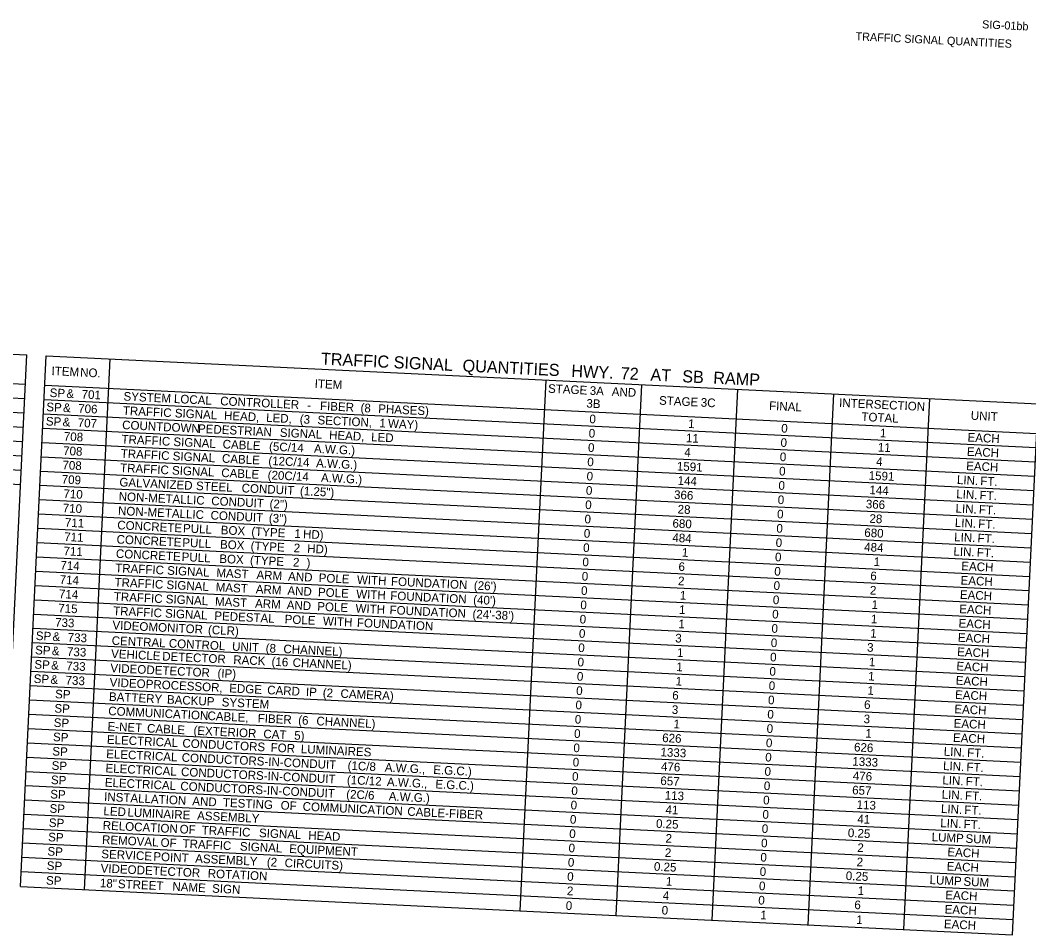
# Model space of a CAD drawing. Extents: x 668933 to 670801, y 741155 to 743955.
# Drawn here: x 669430.3 to 669722.1, y 743470 to 743733.8 of the extents above; entities that cross this region are included whole.
import ezdxf

# ---------------------------------------------------------------- set-up
doc = ezdxf.new("R2010")
doc.units = 0
doc.layers.add('R_Border', color=7, linetype='Continuous')
doc.layers.add('R_Dimension', color=7, linetype='Continuous')

msp = doc.modelspace()

# ---------------------------------------------------------------- linework, layer by layer
at = {"layer": 'R_Dimension'}
for p, q in [((669108.37, 743652.72), (669432.18, 743637)), ((669107.96, 743644.2), (669431.76, 743628.48)), ((669107.76, 743640.06), (669431.56, 743624.34)), ((669424.11, 743470.96), (669432.18, 743637)), ((669430.35, 743483.1), (669437.81, 743636.73)), ((669437.81, 743636.73), (669724.86, 743622.79)), ((669107.56, 743635.92), (669431.36, 743620.2)), ((669448.86, 743482.2), (669456.32, 743635.83)), ((669107.35, 743631.78), (669431.16, 743616.06)), ((669107.15, 743627.65), (669430.96, 743611.92)), ((669437.4, 743628.2), (669724.44, 743614.27)), ((669574.97, 743476.08), (669582.43, 743629.7)), ((669602.72, 743474.73), (669610.18, 743628.35)), ((669630.48, 743473.38), (669637.94, 743627.01)), ((669658.23, 743472.03), (669665.69, 743625.66)), ((669106.95, 743623.51), (669430.76, 743607.78)), ((669437.2, 743624.07), (669724.24, 743610.13)), ((669685.99, 743470.69), (669693.45, 743624.31)), ((669717.4, 743469.16), (669724.86, 743622.79)), ((669106.75, 743619.37), (669430.56, 743603.64)), ((669437, 743619.93), (669724.04, 743605.99)), ((669436.8, 743615.79), (669723.84, 743601.85)), ((669106.55, 743615.23), (669430.36, 743599.51)), ((669436.6, 743611.65), (669723.64, 743597.71)), ((669436.39, 743607.51), (669723.44, 743593.57)), ((669436.19, 743603.37), (669723.24, 743589.43)), ((669435.99, 743599.23), (669723.04, 743585.29)), ((669435.79, 743595.09), (669722.83, 743581.15)), ((669435.59, 743590.95), (669722.63, 743577.02)), ((669435.39, 743586.82), (669722.43, 743572.88)), ((669435.19, 743582.68), (669722.23, 743568.74)), ((669434.99, 743578.54), (669722.03, 743564.6)), ((669434.79, 743574.4), (669721.83, 743560.46)), ((669434.59, 743570.26), (669721.63, 743556.32)), ((669434.38, 743566.12), (669721.43, 743552.18)), ((669434.18, 743561.98), (669721.23, 743548.04)), ((669433.98, 743557.84), (669721.03, 743543.9)), ((669433.78, 743553.7), (669720.82, 743539.77)), ((669433.58, 743549.57), (669720.62, 743535.63)), ((669433.38, 743545.43), (669720.42, 743531.49)), ((669433.18, 743541.29), (669720.22, 743527.35)), ((669432.98, 743537.15), (669720.02, 743523.21)), ((669432.78, 743533.01), (669719.82, 743519.07)), ((669432.58, 743528.87), (669719.62, 743514.93)), ((669432.37, 743524.73), (669719.42, 743510.79)), ((669432.17, 743520.59), (669719.22, 743506.65)), ((669431.97, 743516.45), (669719.02, 743502.52)), ((669431.77, 743512.32), (669718.81, 743498.38)), ((669431.57, 743508.18), (669718.61, 743494.24)), ((669431.37, 743504.04), (669718.41, 743490.1)), ((669431.17, 743499.9), (669718.21, 743485.96)), ((669430.97, 743495.76), (669718.01, 743481.82)), ((669430.77, 743491.62), (669717.81, 743477.68)), ((669430.57, 743487.48), (669717.61, 743473.54)), ((669430.35, 743483.1), (669717.4, 743469.16))]:
    msp.add_line(p, q, dxfattribs=at)

# ---------------------------------------------------------------- texts
at = {"layer": 'R_Border'}
for s, height, p in [('SIG-01bb', 2.345, (669708.56, 743731.51)), ('TRAFFIC SIGNAL QUANTITIES', 2.3448, (669671.93, 743728.04))]:
    msp.add_text(s, height=height, rotation=357.2199, dxfattribs=at).set_placement(p)
at = {"layer": 'R_Dimension'}
for s, height, p in [('TRAFFIC', 3.5, (669517.22, 743634.17)), (' SIGNAL', 3.5, (669536.96, 743633.21)), ('ITEM', 2.5, (669439.28, 743631.13)), (' NO.', 2.5, (669446.63, 743630.77)), (' QUANTITIES', 3.5, (669556.91, 743632.24)), (' HWY.', 3.5, (669588.38, 743630.71)), (' 72', 3.5, (669602.66, 743630.02)), (' AT', 3.5, (669611.28, 743629.6)), (' SB', 3.5, (669620.47, 743629.15)), (' RAMP', 3.5, (669629.45, 743628.72)), ('SP', 2.5, (669438.75, 743624.81)), ('ITEM', 2.5, (669515.43, 743627.43)), ('STAGE', 2.5, (669582.96, 743626.03)), (' 3A', 2.5, (669594.09, 743625.49)), (' AND', 2.5, (669600.46, 743625.18)), (' &', 2.5, (669442.67, 743624.62)), (' 701', 2.5, (669447.05, 743624.41)), ('SYSTEM', 2.5, (669460.12, 743623.77)), (' LOCAL', 2.5, (669473.77, 743623.11)), (' CONTROLLER', 2.5, (669487.16, 743622.46)), ('STAGE', 2.5, (669615.08, 743622.59)), (' 3C', 2.5, (669626.21, 743622.05)), ('INTERSECTION', 2.5, (669667.18, 743621.94)), ('SP', 2.5, (669437.78, 743620.71)), (' &', 2.5, (669441.69, 743620.52)), (' 706', 2.5, (669446.07, 743620.31)), ('TRAFFIC', 2.5, (669459.92, 743619.64)), (' -', 2.5, (669512.33, 743621.24)), (' FIBER', 2.5, (669516.04, 743621.06)), (' (8', 2.5, (669527.76, 743620.49)), (' PHASES)', 2.5, (669532.89, 743620.24)), ('3B', 2.5, (669594.05, 743621.74)), ('FINAL', 2.5, (669646.91, 743621.05)), ('SP', 2.5, (669437.64, 743616.57)), (' &', 2.5, (669441.56, 743616.38)), (' 707', 2.5, (669445.94, 743616.17)), (' SIGNAL', 2.5, (669474.02, 743618.95)), (' HEAD,', 2.5, (669488.27, 743618.26)), (' LED,', 2.5, (669500.45, 743617.67)), (' (3', 2.5, (669510.18, 743617.2)), (' SECTION,', 2.5, (669515.31, 743616.95)), ('0', 2.5, (669594.92, 743617.23)), ('TOTAL', 2.5, (669673.63, 743617.87)), ('UNIT', 2.5, (669705.28, 743618.22)), ('COUNTDOWN', 2.5, (669459.72, 743615.5)), (' PEDESTRIAN', 2.5, (669480.74, 743614.48)), (' SIGNAL', 2.5, (669504.41, 743613.33)), (' 1', 2.5, (669533.22, 743616.08)), (' WAY)', 2.5, (669535.72, 743615.96)), ('0', 2.5, (669594.72, 743613.09)), ('1', 2.5, (669623.49, 743615.84)), ('0', 2.5, (669650.43, 743614.53)), ('1', 2.5, (669679, 743613.15)), ('708', 2.5, (669442.84, 743612.17)), ('TRAFFIC', 2.5, (669459.52, 743611.36)), (' SIGNAL', 2.5, (669473.62, 743610.67)), (' HEAD,', 2.5, (669518.67, 743612.63)), (' LED', 2.5, (669530.84, 743612.04)), ('11', 2.5, (669622.87, 743611.72)), ('0', 2.5, (669650.23, 743610.39)), ('EACH', 2.5, (669704.35, 743611.92)), ('708', 2.5, (669442.64, 743608.03)), (' CABLE', 2.5, (669487.87, 743609.98)), (' (5C/14', 2.5, (669501.3, 743609.33)), (' A.W.G.)', 2.5, (669514.3, 743608.7)), ('0', 2.5, (669594.51, 743608.95)), ('4', 2.5, (669622.38, 743607.6)), ('11', 2.5, (669678.38, 743609.03)), ('EACH', 2.5, (669704.15, 743607.78)), ('TRAFFIC', 2.5, (669459.32, 743607.22)), (' SIGNAL', 2.5, (669473.42, 743606.53)), (' CABLE', 2.5, (669487.67, 743605.84)), (' (12C/14', 2.5, (669501.1, 743605.19)), (' A.W.G.)', 2.5, (669514.92, 743604.52)), ('0', 2.5, (669594.31, 743604.81)), ('0', 2.5, (669650.02, 743606.26)), ('4', 2.5, (669677.89, 743604.9)), ('708', 2.5, (669442.44, 743603.89)), ('TRAFFIC', 2.5, (669459.12, 743603.08)), (' SIGNAL', 2.5, (669473.22, 743602.4)), (' CABLE', 2.5, (669487.47, 743601.7)), ('1591', 2.5, (669620.23, 743603.55)), ('0', 2.5, (669649.82, 743602.12)), ('EACH', 2.5, (669703.95, 743603.64)), ('709', 2.5, (669442.23, 743599.75)), ('GALVANIZED', 2.5, (669458.92, 743598.94)), (' (20C/14', 2.5, (669500.9, 743601.05)), (' A.W.G.)', 2.5, (669516.33, 743600.3)), ('0', 2.5, (669594.11, 743600.67)), ('144', 2.5, (669620.44, 743599.4)), ('1591', 2.5, (669675.74, 743600.86)), ('LIN.', 2.5, (669701.28, 743599.62)), (' FT.', 2.5, (669707.1, 743599.34)), (' STEEL', 2.5, (669480.17, 743597.91)), (' CONDUIT', 2.5, (669493.37, 743597.27)), (' (1.25")', 2.5, (669510.24, 743596.45)), ('0', 2.5, (669593.91, 743596.53)), ('0', 2.5, (669649.62, 743597.98)), ('144', 2.5, (669675.95, 743596.7)), ('710', 2.5, (669442.73, 743595.58)), ('NON-METALLIC', 2.5, (669458.72, 743594.8)), (' CONDUIT', 2.5, (669484.57, 743593.55)), (' (2")', 2.5, (669501.44, 743592.73)), ('366', 2.5, (669619.41, 743595.3)), ('0', 2.5, (669649.42, 743593.84)), ('LIN.', 2.5, (669701.08, 743595.48)), (' FT.', 2.5, (669706.9, 743595.2)), ('710', 2.5, (669442.53, 743591.44)), ('NON-METALLIC', 2.5, (669458.52, 743590.66)), ('0', 2.5, (669593.71, 743592.4)), ('28', 2.5, (669620.45, 743591.1)), ('366', 2.5, (669674.91, 743592.6)), ('LIN.', 2.5, (669700.88, 743591.34)), (' FT.', 2.5, (669706.7, 743591.06)), ('711', 2.5, (669443.15, 743587.26)), (' CONDUIT', 2.5, (669484.37, 743589.41)), (' (3")', 2.5, (669501.24, 743588.59)), ('0', 2.5, (669593.51, 743588.26)), ('680', 2.5, (669618.96, 743587.02)), ('0', 2.5, (669649.22, 743589.7)), ('28', 2.5, (669675.96, 743588.4)), ('LIN.', 2.5, (669700.68, 743587.2)), (' FT.', 2.5, (669706.5, 743586.92)), ('CONCRETE', 2.5, (669458.31, 743586.52)), (' PULL', 2.5, (669476.4, 743585.65)), (' BOX', 2.5, (669487.32, 743585.12)), (' (TYPE', 2.5, (669496.18, 743584.69)), (' 1', 2.5, (669508.63, 743584.08)), ('0', 2.5, (669593.31, 743584.12)), ('0', 2.5, (669649.02, 743585.56)), ('680', 2.5, (669674.47, 743584.33)), ('711', 2.5, (669442.95, 743583.12)), ('CONCRETE', 2.5, (669458.11, 743582.39)), (' PULL', 2.5, (669476.2, 743581.51)), (' HD)', 2.5, (669511.13, 743583.96)), ('484', 2.5, (669618.93, 743582.87)), ('0', 2.5, (669648.82, 743581.42)), ('LIN.', 2.5, (669700.48, 743583.06)), (' FT.', 2.5, (669706.3, 743582.78)), ('711', 2.5, (669442.75, 743578.98)), ('CONCRETE', 2.5, (669457.91, 743578.25)), (' BOX', 2.5, (669487.11, 743580.98)), (' (TYPE', 2.5, (669495.98, 743580.55)), (' 2', 2.5, (669508.43, 743579.94)), (' HD)', 2.5, (669512.34, 743579.75)), ('0', 2.5, (669593.11, 743579.98)), ('1', 2.5, (669621.68, 743578.59)), ('484', 2.5, (669674.44, 743580.18)), ('LIN.', 2.5, (669700.27, 743578.92)), (' FT.', 2.5, (669706.09, 743578.64)), (' PULL', 2.5, (669476, 743577.37)), (' BOX', 2.5, (669486.91, 743576.84)), (' (TYPE', 2.5, (669495.78, 743576.41)), (' 2', 2.5, (669508.23, 743575.8)), (' )', 2.5, (669512.14, 743575.61)), ('0', 2.5, (669592.91, 743575.84)), ('0', 2.5, (669648.62, 743577.28)), ('1', 2.5, (669677.19, 743575.9)), ('714', 2.5, (669441.84, 743574.88)), ('TRAFFIC', 2.5, (669457.71, 743574.11)), (' SIGNAL', 2.5, (669471.81, 743573.42)), (' MAST', 2.5, (669486.06, 743572.73)), ('6', 2.5, (669620.7, 743574.49)), ('0', 2.5, (669648.42, 743573.14)), ('EACH', 2.5, (669702.54, 743574.67)), ('714', 2.5, (669441.64, 743570.74)), ('TRAFFIC', 2.5, (669457.51, 743569.97)), (' ARM', 2.5, (669497.66, 743572.17)), (' AND', 2.5, (669506.81, 743571.72)), (' POLE', 2.5, (669515.66, 743571.29)), (' WITH', 2.5, (669526.72, 743570.76)), (' FOUNDATION', 2.5, (669536.58, 743570.28)), ('0', 2.5, (669592.71, 743571.7)), ('2', 2.5, (669620.57, 743570.35)), ('6', 2.5, (669676.21, 743571.8)), ('EACH', 2.5, (669702.34, 743570.53)), ('714', 2.5, (669441.43, 743566.6)), (' SIGNAL', 2.5, (669471.61, 743569.28)), (' MAST', 2.5, (669485.86, 743568.59)), (' ARM', 2.5, (669497.46, 743568.03)), (' AND', 2.5, (669506.61, 743567.59)), (' POLE', 2.5, (669515.45, 743567.16)), (' WITH', 2.5, (669526.52, 743566.62)), (" (26')", 2.5, (669560.56, 743569.11)), ('0', 2.5, (669592.5, 743567.56)), ('0', 2.5, (669648.22, 743569.01)), ('2', 2.5, (669676.08, 743567.65)), ('TRAFFIC', 2.5, (669457.31, 743565.83)), (' SIGNAL', 2.5, (669471.41, 743565.15)), (' MAST', 2.5, (669485.66, 743564.45)), (' ARM', 2.5, (669497.26, 743563.89)), (' FOUNDATION', 2.5, (669536.37, 743566.14)), (" (40')", 2.5, (669560.36, 743564.97)), ('1', 2.5, (669621.08, 743566.18)), ('0', 2.5, (669648.01, 743564.87)), ('EACH', 2.5, (669702.14, 743566.39)), ('715', 2.5, (669441.23, 743562.46)), ('TRAFFIC', 2.5, (669457.11, 743561.69)), (' SIGNAL', 2.5, (669471.21, 743561.01)), (' AND', 2.5, (669506.41, 743563.45)), (' POLE', 2.5, (669515.25, 743563.02)), (' WITH', 2.5, (669526.32, 743562.48)), (' FOUNDATION', 2.5, (669536.17, 743562)), (" (24'-38')", 2.5, (669560.16, 743560.84)), ('0', 2.5, (669592.3, 743563.42)), ('1', 2.5, (669620.87, 743562.04)), ('0', 2.5, (669647.81, 743560.73)), ('1', 2.5, (669676.59, 743563.48)), ('EACH', 2.5, (669701.94, 743562.25)), ('733', 2.5, (669440.32, 743558.36)), (' PEDESTAL', 2.5, (669485.46, 743560.31)), (' POLE', 2.5, (669505.81, 743559.33)), (' WITH', 2.5, (669516.88, 743558.79)), (' FOUNDATION', 2.5, (669526.73, 743558.31)), ('0', 2.5, (669592.1, 743559.28)), ('1', 2.5, (669620.67, 743557.9)), ('1', 2.5, (669676.38, 743559.34)), ('EACH', 2.5, (669701.74, 743558.11)), ('VIDEO', 2.5, (669456.91, 743557.55)), (' MONITOR', 2.5, (669466.4, 743557.09)), (' (CLR)', 2.5, (669483.63, 743556.26)), ('0', 2.5, (669591.9, 743555.15)), ('0', 2.5, (669647.61, 743556.59)), ('1', 2.5, (669676.18, 743555.2)), ('SP', 2.5, (669434.73, 743554.48)), (' &', 2.5, (669438.64, 743554.29)), (' 733', 2.5, (669443.02, 743554.08)), ('CENTRAL', 2.5, (669456.69, 743553.09)), (' CONTROL', 2.5, (669472.3, 743552.33)), ('3', 2.5, (669619.76, 743553.79)), ('0', 2.5, (669647.41, 743552.45)), ('EACH', 2.5, (669701.54, 743553.97)), ('SP', 2.5, (669434.53, 743550.34)), (' &', 2.5, (669438.44, 743550.15)), (' 733', 2.5, (669442.82, 743549.94)), ('VEHICLE', 2.5, (669456.51, 743549.27)), (' UNIT', 2.5, (669490.61, 743551.45)), (' (8', 2.5, (669500.32, 743550.97)), (' CHANNEL)', 2.5, (669505.45, 743550.72)), ('0', 2.5, (669591.7, 743551.01)), ('1', 2.5, (669620.27, 743549.62)), ('3', 2.5, (669675.27, 743551.1)), ('EACH', 2.5, (669701.34, 743549.83)), ('SP', 2.5, (669434.32, 743546.2)), (' DETECTOR', 2.5, (669470.39, 743548.6)), (' RACK', 2.5, (669490.95, 743547.6)), (' (16', 2.5, (669502.02, 743547.06)), (' CHANNEL)', 2.5, (669508.12, 743546.77)), ('0', 2.5, (669591.5, 743546.87)), ('0', 2.5, (669647.21, 743548.31)), ('1', 2.5, (669675.78, 743546.92)), (' &', 2.5, (669438.24, 743546.01)), (' 733', 2.5, (669442.62, 743545.8)), ('VIDEO', 2.5, (669456.3, 743545.14)), (' DETECTOR', 2.5, (669465.8, 743544.67)), (' (IP)', 2.5, (669486.37, 743543.68)), ('1', 2.5, (669620.07, 743545.48)), ('0', 2.5, (669647.01, 743544.17)), ('EACH', 2.5, (669701.13, 743545.69)), ('SP', 2.5, (669434.12, 743542.06)), (' &', 2.5, (669438.04, 743541.87)), (' 733', 2.5, (669442.42, 743541.66)), ('VIDEO', 2.5, (669456.1, 743541)), (' PROCESSOR,', 2.5, (669465.6, 743540.54)), ('0', 2.5, (669591.3, 743542.73)), ('1', 2.5, (669619.87, 743541.34)), ('1', 2.5, (669675.58, 743542.79)), ('EACH', 2.5, (669700.93, 743541.55)), ('SP', 2.5, (669440.31, 743537.62)), (' EDGE', 2.5, (669489.77, 743539.36)), (' CARD', 2.5, (669500.76, 743538.83)), (' IP', 2.5, (669511.96, 743538.28)), (' (2', 2.5, (669516.84, 743538.05)), (' CAMERA)', 2.5, (669521.97, 743537.8)), ('0', 2.5, (669591.1, 743538.59)), ('6', 2.5, (669618.89, 743537.24)), ('0', 2.5, (669646.81, 743540.03)), ('1', 2.5, (669675.38, 743538.65)), ('EACH', 2.5, (669700.73, 743537.42)), ('BATTERY', 2.5, (669455.9, 743536.86)), (' BACKUP', 2.5, (669471.75, 743536.09)), (' SYSTEM', 2.5, (669487.6, 743535.32)), ('0', 2.5, (669590.9, 743534.45)), ('0', 2.5, (669646.61, 743535.9)), ('6', 2.5, (669674.4, 743534.55)), ('SP', 2.5, (669440.11, 743533.48)), ('COMMUNICATION', 2.5, (669455.7, 743532.72)), ('3', 2.5, (669618.76, 743533.1)), ('0', 2.5, (669646.41, 743531.76)), ('EACH', 2.5, (669700.53, 743533.28)), ('SP', 2.5, (669439.91, 743529.34)), (' CABLE,', 2.5, (669483.48, 743531.37)), (' FIBER', 2.5, (669498.01, 743530.66)), (' (6', 2.5, (669509.73, 743530.1)), (' CHANNEL)', 2.5, (669515, 743529.84)), ('0', 2.5, (669590.7, 743530.31)), ('1', 2.5, (669619.27, 743528.93)), ('3', 2.5, (669674.27, 743530.4)), ('EACH', 2.5, (669700.33, 743529.14)), ('E-NET', 2.5, (669455.49, 743528.26)), (' CABLE', 2.5, (669466, 743527.75)), (' (EXTERIOR', 2.5, (669479.43, 743527.1)), (' CAT', 2.5, (669499.65, 743526.11)), (' 5)', 2.5, (669508.57, 743525.68)), ('0', 2.5, (669590.49, 743526.17)), ('0', 2.5, (669646.21, 743527.62)), ('1', 2.5, (669674.78, 743526.23)), ('SP', 2.5, (669439.71, 743525.2)), ('ELECTRICAL', 2.5, (669455.3, 743524.44)), (' CONDUCTORS', 2.5, (669476.22, 743523.43)), ('626', 2.5, (669615.99, 743524.94)), ('0', 2.5, (669646, 743523.48)), ('EACH', 2.5, (669700.13, 743525)), ('SP', 2.5, (669439.51, 743521.06)), ('ELECTRICAL', 2.5, (669455.1, 743520.3)), (' FOR', 2.5, (669501.76, 743522.19)), (' LUMINAIRES', 2.5, (669510.49, 743521.76)), ('0', 2.5, (669590.29, 743522.04)), ('1333', 2.5, (669615.5, 743520.81)), ('626', 2.5, (669671.5, 743522.24)), ('LIN.', 2.5, (669697.46, 743520.98)), (' FT.', 2.5, (669703.28, 743520.7)), ('SP', 2.5, (669439.31, 743516.92)), (' CONDUCTORS-IN-CONDUIT', 2.5, (669476.02, 743519.29)), (' (1C/8', 2.5, (669524.03, 743516.96)), ('0', 2.5, (669590.09, 743517.9)), ('0', 2.5, (669645.8, 743519.34)), ('1333', 2.5, (669671.01, 743518.12)), ('LIN.', 2.5, (669697.26, 743516.84)), ('ELECTRICAL', 2.5, (669454.9, 743516.16)), (' CONDUCTORS-IN-CONDUIT', 2.5, (669475.82, 743515.15)), (' A.W.G.,', 2.5, (669534.79, 743516.43)), (' E.G.C.)', 2.5, (669548.81, 743515.75)), ('476', 2.5, (669615.65, 743516.66)), ('0', 2.5, (669645.6, 743515.2)), ('476', 2.5, (669671.16, 743513.96)), (' FT.', 2.5, (669703.08, 743516.56)), ('SP', 2.5, (669439.11, 743512.78)), ('ELECTRICAL', 2.5, (669454.7, 743512.03)), (' CONDUCTORS-IN-CONDUIT', 2.5, (669475.62, 743511.01)), (' (1C/12', 2.5, (669523.83, 743512.82)), (' A.W.G.,', 2.5, (669535.41, 743512.25)), (' E.G.C.)', 2.5, (669549.43, 743511.57)), ('0', 2.5, (669589.89, 743513.76)), ('657', 2.5, (669615.45, 743512.52)), ('0', 2.5, (669645.4, 743511.06)), ('LIN.', 2.5, (669697.06, 743512.7)), (' FT.', 2.5, (669702.88, 743512.42)), ('SP', 2.5, (669438.91, 743508.64)), (' (2C/6', 2.5, (669523.63, 743508.68)), ('0', 2.5, (669589.69, 743509.62)), ('113', 2.5, (669616.73, 743508.31)), ('657', 2.5, (669670.96, 743509.82)), ('LIN.', 2.5, (669696.86, 743508.56)), (' FT.', 2.5, (669702.68, 743508.28)), ('INSTALLATION', 2.5, (669454.5, 743507.89)), (' AND', 2.5, (669479.09, 743506.69)), (' TESTING', 2.5, (669487.94, 743506.26)), (' OF', 2.5, (669504.65, 743505.45)), (' A.W.G.)', 2.5, (669535.94, 743508.08)), ('0', 2.5, (669589.49, 743505.48)), ('0', 2.5, (669645.2, 743506.92)), ('113', 2.5, (669672.24, 743505.61)), ('SP', 2.5, (669438.7, 743504.5)), ('LED', 2.5, (669454.3, 743503.75)), (' LUMINAIRE', 2.5, (669460.33, 743503.45)), (' ASSEMBLY', 2.5, (669480.48, 743502.48)), (' COMMUNICATION', 2.5, (669511.02, 743505.14)), (' CABLE-FIBER', 2.5, (669541.3, 743503.67)), ('41', 2.5, (669616.94, 743504.15)), ('0', 2.5, (669645, 743502.78)), ('LIN.', 2.5, (669696.66, 743504.42)), (' FT.', 2.5, (669702.48, 743504.14)), ('SP', 2.5, (669438.5, 743500.37)), ('RELOCATION', 2.5, (669454.09, 743499.61)), ('0', 2.5, (669589.29, 743501.34)), ('0.25', 2.5, (669614.2, 743500.13)), ('41', 2.5, (669672.45, 743501.45)), ('LIN.', 2.5, (669696.46, 743500.29)), (' FT.', 2.5, (669702.28, 743500)), (' OF', 2.5, (669475.43, 743498.57)), (' TRAFFIC', 2.5, (669481.8, 743498.26)), (' SIGNAL', 2.5, (669498.39, 743497.46)), (' HEAD', 2.5, (669512.65, 743496.77)), ('0', 2.5, (669589.09, 743497.2)), ('0', 2.5, (669644.8, 743498.65)), ('0.25', 2.5, (669669.71, 743497.44)), ('SP', 2.5, (669438.3, 743496.23)), ('REMOVAL', 2.5, (669453.89, 743495.47)), (' OF', 2.5, (669469.9, 743494.69)), (' TRAFFIC', 2.5, (669476.27, 743494.38)), (' SIGNAL', 2.5, (669492.86, 743493.58)), ('2', 2.5, (669616.95, 743495.85)), ('0', 2.5, (669644.6, 743494.51)), ('LUMP', 2.5, (669693.96, 743496.26)), (' SUM', 2.5, (669702.83, 743495.83)), ('SP', 2.5, (669438.1, 743492.09)), ('SERVICE', 2.5, (669453.69, 743491.33)), (' POINT', 2.5, (669467.81, 743490.65)), (' EQUIPMENT', 2.5, (669507.12, 743492.89)), ('0', 2.5, (669588.89, 743493.06)), ('2', 2.5, (669616.75, 743491.71)), ('2', 2.5, (669672.46, 743493.15)), ('EACH', 2.5, (669698.52, 743491.89)), ('SP', 2.5, (669437.9, 743487.95)), (' ASSEMBLY', 2.5, (669479.92, 743490.06)), (' (2', 2.5, (669500.66, 743489.05)), (' CIRCUITS)', 2.5, (669505.8, 743488.8)), ('0', 2.5, (669588.69, 743488.92)), ('0.25', 2.5, (669613.6, 743487.71)), ('0', 2.5, (669644.4, 743490.37)), ('2', 2.5, (669672.26, 743489.01)), ('EACH', 2.5, (669698.32, 743487.75)), ('VIDEO', 2.5, (669453.49, 743487.19)), (' DETECTOR', 2.5, (669462.99, 743486.73)), (' ROTATION', 2.5, (669483.55, 743485.73)), ('0', 2.5, (669588.49, 743484.79)), ('0', 2.5, (669644.2, 743486.23)), ('0.25', 2.5, (669669.11, 743485.02)), ('SP', 2.5, (669437.69, 743483.69)), ('18"', 2.5, (669453.28, 743482.93)), (' STREET', 2.5, (669457.55, 743482.72)), (' NAME', 2.5, (669473.32, 743481.96)), ('1', 2.5, (669617.06, 743483.4)), ('0', 2.5, (669643.99, 743482.09)), ('LUMP', 2.5, (669693.36, 743483.84)), (' SUM', 2.5, (669702.23, 743483.41)), (' SIGN', 2.5, (669484.82, 743481.4)), ('2', 2.5, (669588.39, 743480.64)), ('4', 2.5, (669616.15, 743479.29)), ('1', 2.5, (669672.57, 743480.7)), ('EACH', 2.5, (669697.92, 743479.47)), ('0', 2.5, (669588.08, 743476.39)), ('0', 2.5, (669643.79, 743477.95)), ('6', 2.5, (669671.59, 743476.6)), ('0', 2.5, (669615.83, 743475.04)), ('1', 2.5, (669644.4, 743473.65)), ('EACH', 2.5, (669697.72, 743475.33)), ('1', 2.5, (669672.16, 743472.3)), ('EACH', 2.5, (669697.51, 743471.07))]:
    msp.add_text(s, height=height, rotation=357.2199, dxfattribs=at).set_placement(p)

doc.saveas('drawing.dxf')
